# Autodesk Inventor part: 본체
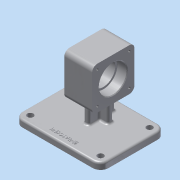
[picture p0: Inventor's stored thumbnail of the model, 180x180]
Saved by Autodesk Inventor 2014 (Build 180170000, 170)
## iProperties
Created: 2020-11
Part Number: 본체
Material: 알루미늄 6061
Document SubType Name: Modeling
Designer: kh
Density: 2.71 g/cm^3
Appearance: 알루미늄 - 평지
Mass: 685.745 g
Surface Area: 542.794 cm^2
Volume: 253.042 cm^3
Author: kh
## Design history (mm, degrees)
sketch "스케치1"
  geometry: L1 (63.86, -49)-(-66.14, -49); L2 (-66.14, -49)-(-66.14, 49); L3 (-66.14, 49)-(63.86, 49); L4 (63.86, 49)-(63.86, -49); L5 (63.86, -49)-(-66.14, 49); L6 (-66.14, -49)-(63.86, 49); 2 further points
  constraints: 12 end point, 2 midpoint, 2 parallel, 1 horizontal, 1 perpendicular
  dimensions: "d0" = 130 distance of L2.end L3.end; "d1" = 98 distance of L1.end L2.end
extrude "돌출1" new body sketch "스케치1" distance "d2" = 10; taper "d3" = 0 deg
sketch "스케치3"
  geometry: 1 further point
sketch "스케치4"
  geometry: L1 (-19, 102)-(45, 102); L2 (45, 102)-(45, 38); L3 (45, 38)-(-19, 38); L4 (-19, 38)-(-19, 102); L5 (-19, 102)-(45, 38); L6 (45, 102)-(-19, 38); L7 (49, 0)-(-49, 0) reference; L8 (49, 0)-(49, 10) reference; L9 (-49, 10)-(49, 10) reference; L10 (-49, 0)-(-49, 10) reference; L11 (49, 0)-(-49, 0) reference; 4 further points
  constraints: 12 end point, 2 midpoint, 2 parallel, 1 coincident, 1 horizontal, 1 perpendicular
  dimensions: "d4" = 64 distance of L1.start L1.end; "d5" = 64 distance of L3.end L1.start; "d43" = 62 distance from line of L10 point (13, 70); "d122" = 70 distance from line of L7 point (13, 70)
extrude "돌출2" join sketch "스케치4" stored distance "d7" = 42; taper "d8" = 0 deg
sketch "스케치9"
  geometry: L1 (-102, 45)-(-102, -19) reference; L2 (-102, -19)-(-38, -19) reference; L3 (-38, -19)-(-38, 45) reference; L4 (-38, 45)-(-102, 45) reference; L5 (0, 49)-(0, -49) reference; C1 r 18 at (-70, 13); 1 further point
  constraints: 1 centre point
  dimensions: "d46" = 36 diameter of C1; "d123" = 70 distance from line of C1.centre L5
extrude "돌출4" cut sketch "스케치9" distance "d47" = 42; taper "d48" = 0 deg
hole "구멍4" diameter "d51" = 42; stored, may be unused: countersink angle "d55" = 90 deg, drill point angle "d57" = 0 deg; dims "d49" = 10, "d50" = 10, "d52" = 8, "d53" = 42, "d54" = 15, "d56" = 15
sketch "스케치11"
  geometry: L1 (33, 38)-(33, 10); L2 (-19, 102)-(45, 102) reference; L3 (45, 102)-(45, 38) reference; L4 (45, 38)-(-19, 38) reference; L5 (-19, 38)-(-19, 102) reference; L6 (-49, 0)-(49, 0) reference; L7 (-49, 0)-(-49, 10) reference; L8 (49, 10)-(-49, 10) reference; L9 (49, 0)-(49, 10) reference; L10 (13, 70)-(13, 107.568); L11 (-7, 38)-(-7, 10); L12 (-7, 38)-(33, 38); L13 (-7, 10)-(33, 10); C1 r 21 at (13, 70) reference; 1 further point
  constraints: 10 end point, 2 collinear, 2 point on line, 2 symmetric about line, 1 parallel, 1 vertical
  dimensions: "d60" = 20 distance between parallel lines of L1 L10
extrude "돌출5" join sketch "스케치11" stored distance "d61" = 8; taper "d62" = 0 deg
node "작업 평면2"
sketch "스케치18"
  geometry: L1 (38, 64)-(38, 92); L2 (42, 64)-(0, 64) reference; L3 (42, 0)-(42, 64) reference; L4 (0, 0)-(42, 0) reference; L5 (0, 64)-(0, 0) reference; L6 (0, 0)-(42, 0) reference; L7 (42, 0)-(0, 0) reference; L8 (42, 64)-(42, 0) reference; L9 (42, 64)-(0, 64) reference; L10 (0, 0)-(0, 64) reference; L11 (-45.14, 102)-(84.86, 102) reference; L12 (-45.14, 102)-(-45.14, 92) reference; L13 (84.86, 92)-(-45.14, 92) reference; L14 (84.86, 102)-(84.86, 92) reference; 1 further point
  constraints: 2 end point, 2 point on line, 1 vertical
  dimensions: "d74" = 17 horizontal distance of point (21, 102) L1.end
feature "리브2" sketch "스케치18" dims "d75" = 1, "d76" = 8, "d77" = 0, "d78" = 0, "d79" = 1, "d80" = 1
sketch "스케치19"
  geometry: L1 (-102, 45)-(-102, -19) reference; L2 (-102, -19)-(-38, -19) reference; L3 (-38, -19)-(-38, 45) reference; L4 (-38, 45)-(-102, 45) reference; C1 r 21 at (-70, 13) reference; 2 further points
  dimensions: "d81" = 24 horizontal distance of C1.centre point (-94, -11); "d82" = 24 horizontal distance of C1.centre point (-94, -11)
hole "구멍5" sketch "스케치19" at (-94, -11) diameter "d83" = 3.242; stored, may be unused: countersink angle "d87" = 90 deg, drill point angle "d89" = 118 deg; dims "d84" = 8, "d85" = 42, "d86" = 15, "d88" = 10
fillet "모깎기1" dims "d96" = 12
hole "구멍6" diameter "d99" = 9; stored, may be unused: countersink angle "d103" = 90 deg, drill point angle "d105" = 0 deg; dims "d97" = 10, "d98" = 10, "d100" = 8, "d101" = 42, "d102" = 15, "d104" = 10
fillet "모깎기2" dims "d110" = 0.3
fillet "모깎기3" dims "d111" = 8
fillet "모깎기4" dims "d112" = 3
fillet "모깎기5" dims "d113" = 3
fillet "모깎기6" dims "d114" = 3
sketch "스케치20" dims "d49" = 10, "d50" = 10
  geometry: L1 (-66.14, 37)-(-66.14, -37) reference; L2 (-54.14, -49)-(51.86, -49) reference; 2 further points
  constraints: 1 other
  dimensions: "d115" = 65 distance from line of L1 point (-1.14, -39); "d116" = 10 distance from line of L2 point (-1.14, -39)
feature "엠보싱1" sketch "스케치20" dims "d0" = 130, "d1" = 98, "d117" = 0.5, "d118" = 0
chamfer "모따기1" distance "d119" = 1; stored, may be unused: second distance "d120" = 2, angle "d121" = 45 deg
node "솔리드1"
mirror "대칭2"
mirror "대칭3"
pattern_linear "직사각형 패턴2" dims "d92" = 48, "d95" = 48
mirror "대칭4"
pattern_linear "직사각형 패턴3"
node "투영된 루프1"
node "투영된 루프6"
node "투영된 루프7"
node "투영된 루프8"
node "투영된 루프14"
node "투영된 루프15"
node "투영된 루프16"
node "투영된 루프17"
other parameters: "d73" = -32
